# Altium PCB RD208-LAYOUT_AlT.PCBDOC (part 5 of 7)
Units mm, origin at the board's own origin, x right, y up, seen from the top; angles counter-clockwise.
Board outline 240 x 150 mm, 6 copper layers (TOP, Mid-Layer 1, Mid-Layer 2, Mid-Layer 3, Mid-Layer 4, BOTTOM), stack 1.422 mm thick; 773 components, 409 nets, 3936 pads, 97 vias.
Unrouted connection lines stored in the file: 1.
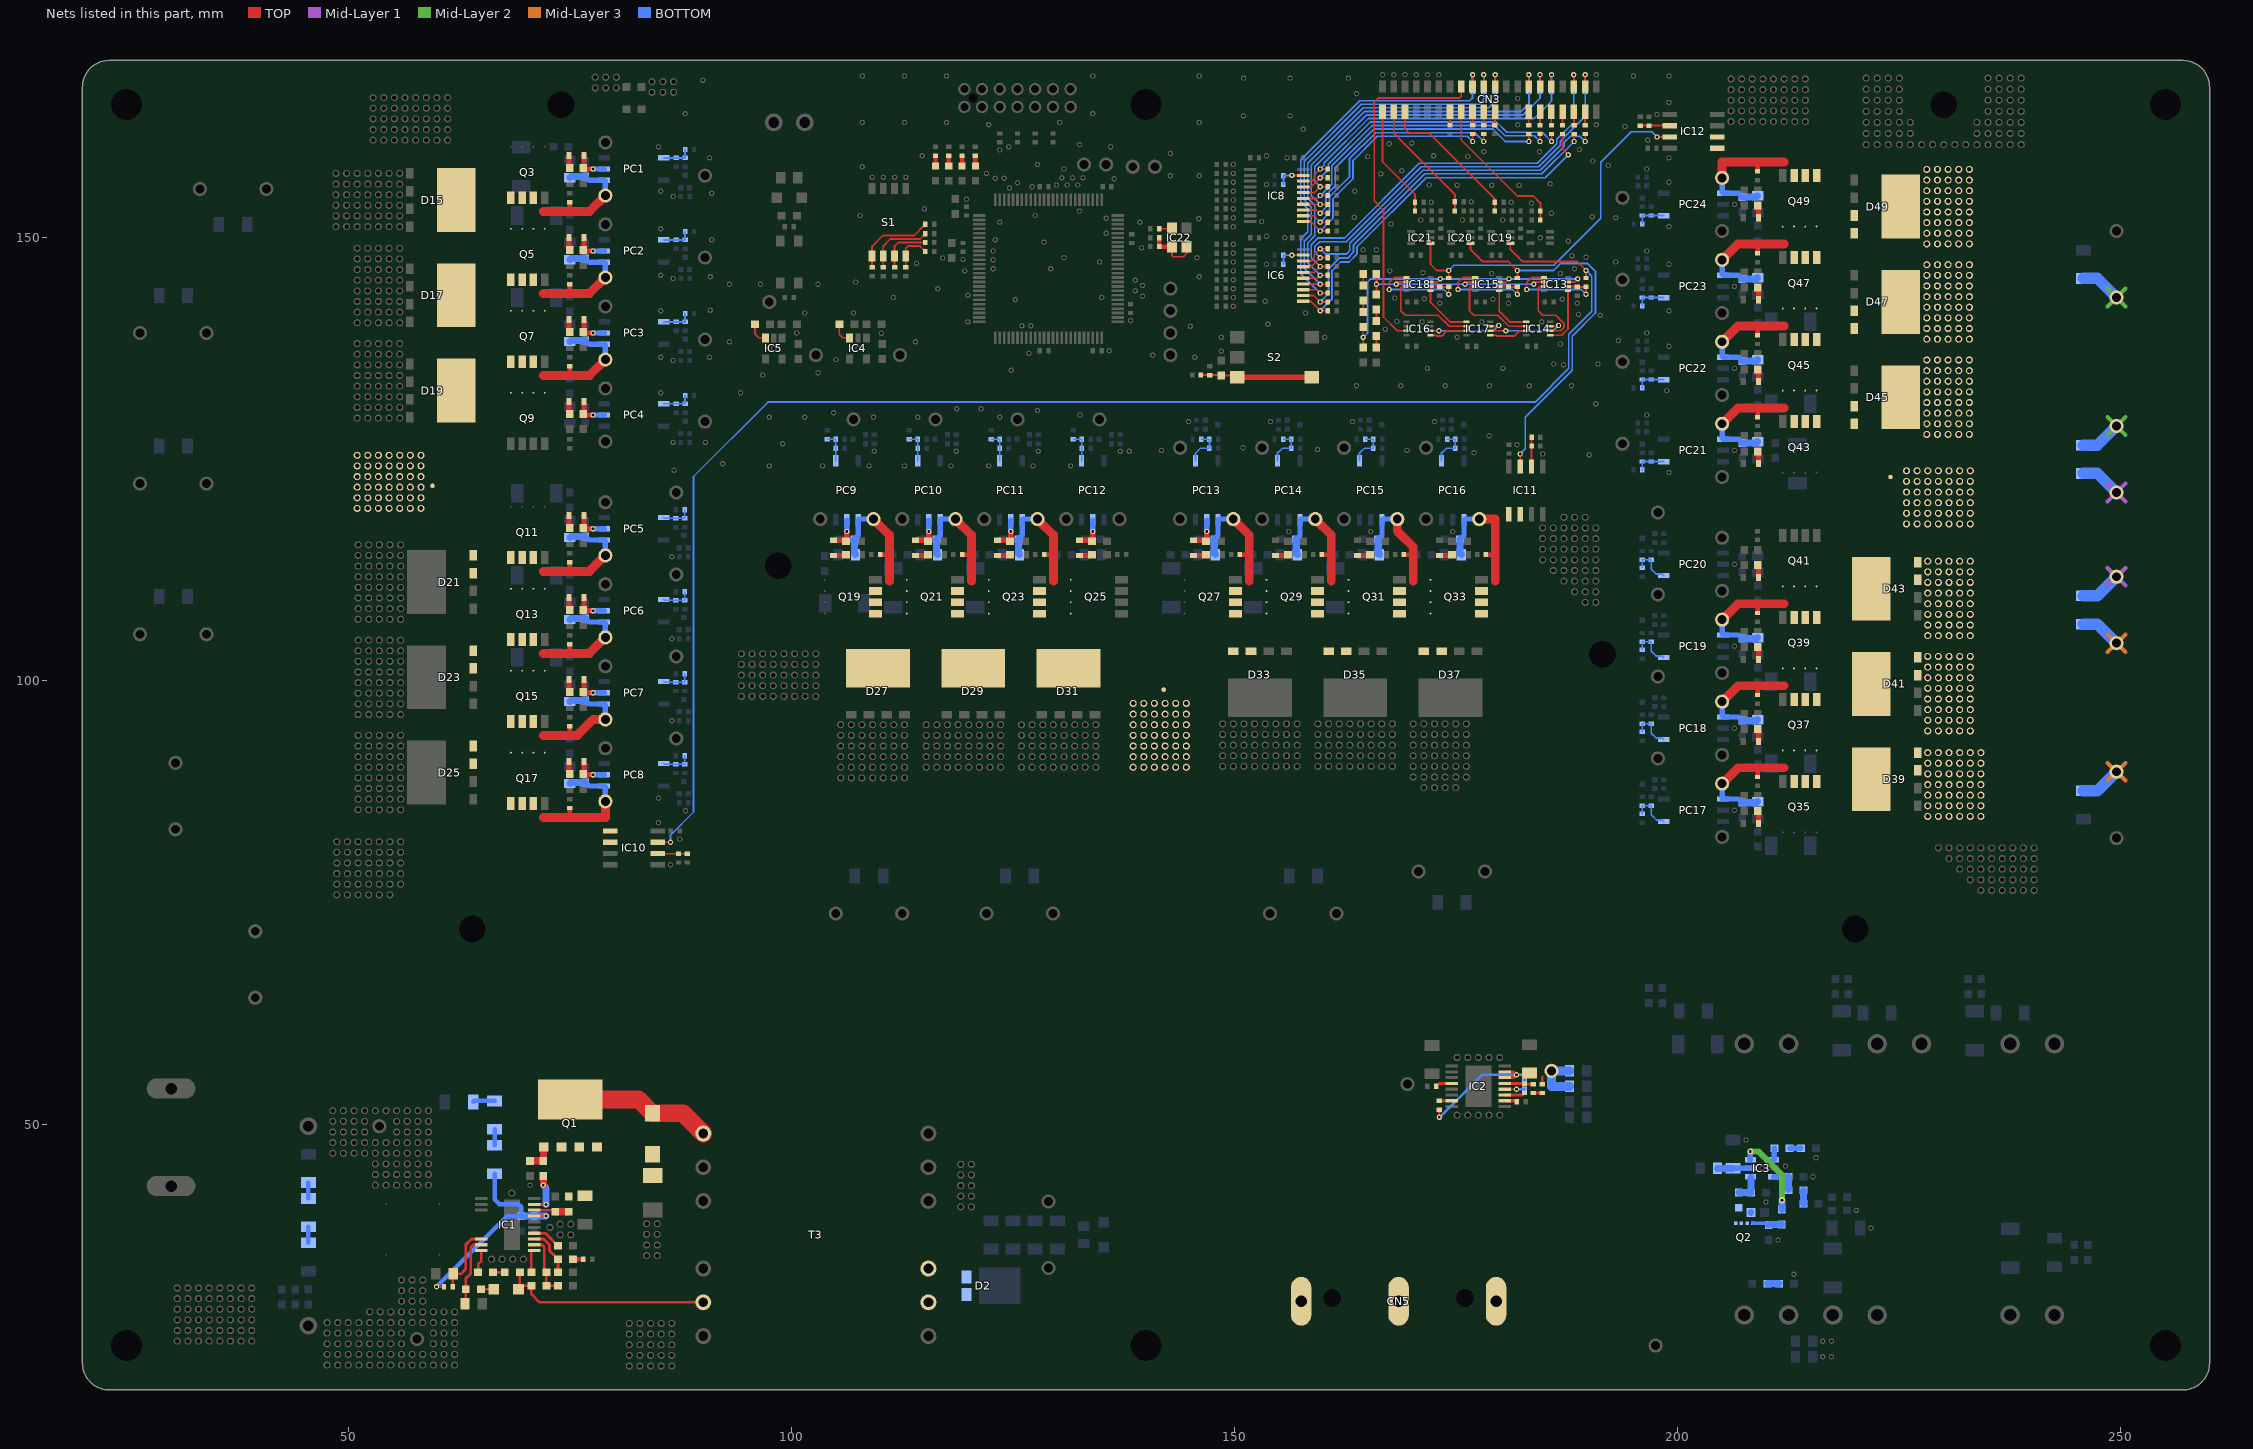
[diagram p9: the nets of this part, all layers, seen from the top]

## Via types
v1: diameter 0.7, hole 0.3, TOP to BOTTOM, 92 vias
v2: diameter 0.9, hole 0.5, TOP to BOTTOM, 4 vias
v3: diameter 1.6, hole 1, TOP to BOTTOM, 1 vias

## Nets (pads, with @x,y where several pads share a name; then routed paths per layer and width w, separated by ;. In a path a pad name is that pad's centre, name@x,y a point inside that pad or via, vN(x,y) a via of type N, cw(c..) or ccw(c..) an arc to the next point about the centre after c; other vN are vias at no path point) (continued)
HVW_1_4: C82.2 C84.1 D43.3 D43.4 D49.5 pad.@228.1,149.3 pad.@228.1,150.5 pad.@228.1,151.7 pad.@228.1,152.9 pad.@228.1,154.1 pad.@228.1,155.3 pad.@228.1,156.5 pad.@228.1,157.7 pad.@228.2,105.1 pad.@228.2,106.3 pad.@228.2,107.5 pad.@228.2,108.7 pad.@228.2,109.9 pad.@228.2,111.1 pad.@228.2,112.3 pad.@228.2,113.5 pad.@229.3,149.3 pad.@229.3,150.5 pad.@229.3,151.7 pad.@229.3,152.9 pad.@229.3,154.1 pad.@229.3,155.3 pad.@229.3,156.5 pad.@229.3,157.7 pad.@229.4,105.1 pad.@229.4,106.3 pad.@229.4,107.5 pad.@229.4,108.7 pad.@229.4,109.9 pad.@229.4,111.1 pad.@229.4,112.3 pad.@229.4,113.5 pad.@230.5,149.3 pad.@230.5,150.5 pad.@230.5,151.7 pad.@230.5,152.9 pad.@230.5,154.1 pad.@230.5,155.3 pad.@230.5,156.5 pad.@230.5,157.7 pad.@230.6,105.1 pad.@230.6,106.3 pad.@230.6,107.5 pad.@230.6,108.7 pad.@230.6,109.9 pad.@230.6,111.1 pad.@230.6,112.3 pad.@230.6,113.5 pad.@231.7,149.3 pad.@231.7,150.5 pad.@231.7,151.7 pad.@231.7,152.9 pad.@231.7,154.1 pad.@231.7,155.3 pad.@231.7,156.5 pad.@231.7,157.7 pad.@231.8,105.1 pad.@231.8,106.3 pad.@231.8,107.5 pad.@231.8,108.7 pad.@231.8,109.9 pad.@231.8,111.1 pad.@231.8,112.3 pad.@231.8,113.5 pad.@232.9,149.3 pad.@232.9,150.5 pad.@232.9,151.7 pad.@232.9,152.9 pad.@232.9,154.1 pad.@232.9,155.3 pad.@232.9,156.5 pad.@232.9,157.7 pad.@233,105.1 pad.@233,106.3 pad.@233,107.5 pad.@233,108.7 pad.@233,109.9 pad.@233,111.1 pad.@233,112.3 pad.@233,113.5 R205.2 R206.1 | length 20.6
  Mid-Layer 2 w0.44: 248.5,127.75 C82.2@249.5,128.75 ; 248.5,129.75 C82.2@249.5,128.75 ; 248.5,142.25 C84.1@249.5,143.25 ; 248.5,144.25 C84.1@249.5,143.25 ; 250.5,127.75 C82.2@249.5,128.75 ; 250.5,129.75 C82.2@249.5,128.75 ; 250.5,142.25 C84.1@249.5,143.25 ; 250.5,144.25 C84.1@249.5,143.25
  BOTTOM w1.3: R205.2@245.75,126.6 247.35,126.6 C82.2@249.5,128.75 ; R206.1@245.75,145.4 247.35,145.4 C84.1@249.5,143.25
HVW_2_4: C80.2 C82.1 D41.3 D41.4 D47.5 pad.@228.1,138.55 pad.@228.1,139.75 pad.@228.1,140.95 pad.@228.1,142.15 pad.@228.1,143.35 pad.@228.1,144.55 pad.@228.1,145.75 pad.@228.1,146.95 pad.@228.2,94.35 pad.@228.2,95.55 pad.@228.2,96.75 pad.@228.2,97.95 pad.@228.2,99.15 pad.@228.2,100.35 pad.@228.2,101.55 pad.@228.2,102.75 pad.@229.3,138.55 pad.@229.3,139.75 pad.@229.3,140.95 pad.@229.3,142.15 pad.@229.3,143.35 pad.@229.3,144.55 pad.@229.3,145.75 pad.@229.3,146.95 pad.@229.4,94.35 pad.@229.4,95.55 pad.@229.4,96.75 pad.@229.4,97.95 pad.@229.4,99.15 pad.@229.4,100.35 pad.@229.4,101.55 pad.@229.4,102.75 pad.@230.5,138.55 pad.@230.5,139.75 pad.@230.5,140.95 pad.@230.5,142.15 pad.@230.5,143.35 pad.@230.5,144.55 pad.@230.5,145.75 pad.@230.5,146.95 pad.@230.6,94.35 pad.@230.6,95.55 pad.@230.6,96.75 pad.@230.6,97.95 pad.@230.6,99.15 pad.@230.6,100.35 pad.@230.6,101.55 pad.@230.6,102.75 pad.@231.7,138.55 pad.@231.7,139.75 pad.@231.7,140.95 pad.@231.7,142.15 pad.@231.7,143.35 pad.@231.7,144.55 pad.@231.7,145.75 pad.@231.7,146.95 pad.@231.8,94.35 pad.@231.8,95.55 pad.@231.8,96.75 pad.@231.8,97.95 pad.@231.8,99.15 pad.@231.8,100.35 pad.@231.8,101.55 pad.@231.8,102.75 pad.@232.9,138.55 pad.@232.9,139.75 pad.@232.9,140.95 pad.@232.9,142.15 pad.@232.9,143.35 pad.@232.9,144.55 pad.@232.9,145.75 pad.@232.9,146.95 pad.@233,94.35 pad.@233,95.55 pad.@233,96.75 pad.@233,97.95 pad.@233,99.15 pad.@233,100.35 pad.@233,101.55 pad.@233,102.75 R204.2 R205.1 | length 20.6
  Mid-Layer 1 w0.44: 248.5,110.75 C80.2@249.5,111.75 ; 248.5,112.75 C80.2@249.5,111.75 ; 248.5,120.25 C82.1@249.5,121.25 ; 248.5,122.25 C82.1@249.5,121.25 ; 250.5,110.75 C80.2@249.5,111.75 ; 250.5,112.75 C80.2@249.5,111.75 ; 250.5,120.25 C82.1@249.5,121.25 ; 250.5,122.25 C82.1@249.5,121.25
  BOTTOM w1.3: R204.2@245.75,109.6 247.35,109.6 C80.2@249.5,111.75 ; R205.1@245.75,123.4 247.35,123.4 C82.1@249.5,121.25
HVW_3_4: C78.2 C80.1 D39.3 D39.4 D45.5 pad.@228.1,127.8 pad.@228.1,129 pad.@228.1,130.2 pad.@228.1,131.4 pad.@228.1,132.6 pad.@228.1,133.8 pad.@228.1,135 pad.@228.1,136.2 pad.@228.2,84.7 pad.@228.2,85.9 pad.@228.2,87.1 pad.@228.2,88.3 pad.@228.2,89.5 pad.@228.2,90.7 pad.@228.2,91.9 pad.@229.3,127.8 pad.@229.3,129 pad.@229.3,130.2 pad.@229.3,131.4 pad.@229.3,132.6 pad.@229.3,133.8 pad.@229.3,135 pad.@229.3,136.2 pad.@229.4,84.7 pad.@229.4,85.9 pad.@229.4,87.1 pad.@229.4,88.3 pad.@229.4,89.5 pad.@229.4,90.7 pad.@229.4,91.9 pad.@230.5,127.8 pad.@230.5,129 pad.@230.5,130.2 pad.@230.5,131.4 pad.@230.5,132.6 pad.@230.5,133.8 pad.@230.5,135 pad.@230.5,136.2 pad.@230.6,84.7 pad.@230.6,85.9 pad.@230.6,87.1 pad.@230.6,88.3 pad.@230.6,89.5 pad.@230.6,90.7 pad.@230.6,91.9 pad.@231.7,127.8 pad.@231.7,129 pad.@231.7,130.2 pad.@231.7,131.4 pad.@231.7,132.6 pad.@231.7,133.8 pad.@231.7,135 pad.@231.7,136.2 pad.@231.8,84.7 pad.@231.8,85.9 pad.@231.8,87.1 pad.@231.8,88.3 pad.@231.8,89.5 pad.@231.8,90.7 pad.@231.8,91.9 pad.@232.9,127.8 pad.@232.9,129 pad.@232.9,130.2 pad.@232.9,131.4 pad.@232.9,132.6 pad.@232.9,133.8 pad.@232.9,135 pad.@232.9,136.2 pad.@233,84.7 pad.@233,85.9 pad.@233,87.1 pad.@233,88.3 pad.@233,89.5 pad.@233,90.7 pad.@233,91.9 pad.@234.2,84.7 pad.@234.2,85.9 pad.@234.2,87.1 pad.@234.2,88.3 pad.@234.2,89.5 pad.@234.2,90.7 pad.@234.2,91.9 R203.2 R204.1 | length 20.6
  Mid-Layer 3 w0.44: 248.5,88.75 C78.2@249.5,89.75 ; 248.5,90.75 C78.2@249.5,89.75 ; 248.5,103.25 C80.1@249.5,104.25 ; 248.5,105.25 C80.1@249.5,104.25 ; 250.5,88.75 C78.2@249.5,89.75 ; 250.5,90.75 C78.2@249.5,89.75 ; 250.5,103.25 C80.1@249.5,104.25 ; 250.5,105.25 C80.1@249.5,104.25
  BOTTOM w1.3: R203.2@245.75,87.6 247.35,87.6 C78.2@249.5,89.75 ; R204.1@245.75,106.4 247.35,106.4 C80.1@249.5,104.25
ILIM_H: IC13.3 IC15.3 IC18.3 pad.@164.5,138.75 pad.@173.2,145.35 pad.@180.95,145.35 pad.@188.7,145.35 R129.2 R131.1 | length 36.3
  TOP w0.2: R129.2@164.5,137.6 pad.@164.5,138.75 R131.1@164.5,139.9 ; IC18.3@172.1,145 172.85,145 pad.@173.2,145.35 ; IC15.3@179.85,145 180.6,145 pad.@180.95,145.35 ; IC13.3@187.6,145 188.35,145 pad.@188.7,145.35
  BOTTOM w0.2: pad.@164.5,138.75 165,139.25 165,145 165.35,145.35 pad.@173.2,145.35 pad.@180.95,145.35 pad.@188.7,145.35
ILIM_L: IC13.6 IC15.6 IC18.6 pad.@166,144.75 pad.@168.25,144.75 pad.@176,144.75 pad.@183.75,144.75 R132.2 R134.1 | length 23.8
  TOP w0.2: R132.2@166,143.6 pad.@166,144.75 R134.1@166,145.9 ; pad.@168.25,144.75 168.5,145 IC18.6@169.4,145 ; pad.@176,144.75 176.25,145 IC15.6@177.15,145 ; pad.@183.75,144.75 184,145 IC13.6@184.9,145
  BOTTOM w0.2: pad.@166,144.75 pad.@168.25,144.75 pad.@176,144.75 pad.@183.75,144.75
ISEN_U: IC10.7 IC19.1 pad.@86.35,81.785 pad.@189.65,146.3 R309.2 | length 171
  TOP w0.2: IC10.7@84.932,81.785 pad.@86.35,81.785 ; IC19.1@181.1,149.35 181.1,148.7 182.5,147.3 188.65,147.3 pad.@189.65,146.3 R309.2@189.65,145.45
  BOTTOM w0.2: pad.@86.35,81.785 86.35,82.6 88.95,85.2 88.95,123.05 97.35,131.45 183.9,131.45 187.7,135.25 187.7,139.1 190.3,141.7 190.3,145.65 pad.@189.65,146.3
ISEN_U_FLT: C139.1 IC13.2 IC13.5 pad.@182.95,144.15 pad.@189.65,143.6 R309.1 | length 12.8
  TOP w0.2: pad.@182.95,144.15 182.95,144.95 183.5,145.5 IC13.5@184.9,145.5 ; IC13.2@187.6,144.5 188.6,144.5 C139.1@188.65,144.45 R309.1@189.65,144.45 pad.@189.65,143.6
  BOTTOM w0.2: pad.@182.95,144.15 189.1,144.15 pad.@189.65,143.6
ISEN_V: IC11.7 IC20.1 pad.@181.9,146.3 pad.@182.215,125.6 R310.2 | length 42.8
  TOP w0.2: IC20.1@176.6,149.35 176.6,148.7 178,147.3 180.9,147.3 pad.@181.9,146.3 R310.2@181.9,145.45 ; IC11.7@182.215,124.182 pad.@182.215,125.6
  BOTTOM w0.2: pad.@181.9,146.3 186,146.3 186.8,147.1 189.8,147.1 190.7,146.2 190.7,141.5 188.1,138.9 188.1,135.05 182.8,129.75 182.8,126.185 pad.@182.215,125.6
ISEN_V_FLT: C140.1 IC15.2 IC15.5 pad.@175.2,144.15 pad.@181.9,143.6 R310.1 | length 12.8
  TOP w0.2: pad.@175.2,144.15 175.2,144.95 175.75,145.5 IC15.5@177.15,145.5 ; IC15.2@179.85,144.5 180.85,144.5 C140.1@180.9,144.45 R310.1@181.9,144.45 pad.@181.9,143.6
  BOTTOM w0.2: pad.@175.2,144.15 181.35,144.15 pad.@181.9,143.6
ISEN_W: IC12.7 IC21.1 pad.@174.15,146.3 pad.@197.65,161.365 R311.2 | length 40.9
  TOP w0.2: IC21.1@172.1,149.35 172.1,147 172.8,146.3 pad.@174.15,146.3 R311.2@174.15,145.45 ; pad.@197.65,161.365 IC12.7@199.067,161.365
  BOTTOM w0.2: pad.@174.15,146.3 174.75,146.9 186,146.9 191.3,152.2 191.3,158.5 194.75,161.95 197.065,161.95 pad.@197.65,161.365
ISEN_W_FLT: C141.1 IC18.2 IC18.5 pad.@167.45,144.15 pad.@174.15,143.6 R311.1 | length 12.8
  TOP w0.2: pad.@167.45,144.15 167.45,144.95 168,145.5 IC18.5@169.4,145.5 ; IC18.2@172.1,144.5 173.1,144.5 C141.1@173.15,144.45 R311.1@174.15,144.45 pad.@174.15,143.6
  BOTTOM w0.2: pad.@167.45,144.15 173.6,144.15 pad.@174.15,143.6
L3803_FB: IC3.3 R29.2 R34.1 | length 3.1
  BOTTOM w0.6: IC3.3@210.81,44.05 R34.1@212.5,44.05
  BOTTOM w0.8: R29.2@212.5,42.6 R34.1@212.5,44.05
L3803_NGATE: IC3.6 R154.1 | length 9.5
  Mid-Layer 2 w0.7: v1(208.19,46.9) 209.1,46.9 211.75,44.25 v1(211.75,41.4)
  BOTTOM w0.6: IC3.6@208.19,45.95 v1(208.19,46.9)
  BOTTOM w0.8: R154.1@211.75,40.35 v1(211.75,41.4)
L3803_SENSE: C103.1 IC3.4 R30.1 | length 3.1
  BOTTOM w0.8: R30.1@206.9,42.25 C103.1@208.25,42.25 IC3.4@208.25,43.95
L3803_VCC: C129.1 IC3.5 R155.2 | length 3.7
  BOTTOM w0.6: C129.1@206.25,45 IC3.5@208.19,45
  BOTTOM w0.8: R155.2@204.475,45 C129.1@206.25,45
LDO_15V_CDC: IC2.3 R296.1 | length 2.3
  TOP w0.3: IC2.3@180.488,53.275 182.475,53.275 R296.1@182.7,53.5
LDO_15V_ILIM: IC2.2 R26.1 | length 1.4
  TOP w0.35: IC2.2@180.488,52.625 181.725,52.625 R26.1@181.85,52.5
LDO_15V_SET: IC2.5 R27.2 R296.2 | length 3.2
  TOP w0.3: IC2.5@180.488,54.575 182.625,54.575 R296.2@182.7,54.5 R27.2@183.7,54.5
LDO_15V_STD_N: IC2.12 R22.2 | length 1.9
  TOP w0.3: R22.2@172.75,54.25 173.075,54.575 IC2.12@174.513,54.575
LDO_15VOUT: C16.1 IC2.6 IC2.7 pad.@173.1,50.75 pad.@181.8,55.55 R21.1 R24.2 R25.1 R295.1 R297.2 TP4.1 | length 22.5
  TOP w0.3: pad.@173.1,50.75 R295.1@173.1,51.6 ; R24.2@184.7,54.5 184.7,55.35
  TOP w0.35: IC2.6@180.488,55.225 181.475,55.225 pad.@181.8,55.55 181.475,55.875 IC2.7@180.488,55.875
  BOTTOM w0.3: pad.@173.1,50.75 177.9,55.55 pad.@181.8,55.55 182.55,55.55 182.7,55.4 R297.2@182.7,54.95
  BOTTOM w1: R25.1@187.775,54.25 185.75,54.25 TP4.1@185.75,56 R21.1@187.775,56
LT8316_BIAS: C4.1 IC1.9 R2.1 | length 8
  TOP w0.3: C4.1@63.175,29.7 63.25,29.775 R2.1@63.25,31.35 63.25,32.55 63.8,33.1 63.8,36.05 64.125,36.375 IC1.9@65.012,36.375
LT8316_DCM: IC1.10 R4.2 | length 2.6
  TOP w0.3: R4.2@64.65,33.25 64.65,34.2 65.012,34.562 IC1.10@65.012,35.725
LT8316_EN: C8.2 IC1.17 pad.@59.95,31.65 pad.@72.3,39.625 R7.2 R11.2 R312.2 | length 25.1
  TOP w0.3: pad.@59.95,31.65 R312.2@60.8,31.65 ; IC1.17@70.988,39.625 pad.@72.3,39.625
  BOTTOM w0.5: pad.@59.95,31.65 67.9,39.6 R11.2@69.5,39.6 69.5,40.65 69.2,40.95 67.05,40.95 66.5,41.5 R7.2@66.5,44.4
  BOTTOM w0.8: R11.2@69.5,39.6 C8.2@71,39.6 71.025,39.625 pad.@72.3,39.625
LT8316_FB: IC1.12 R6.2 R12.1 R13.1 | length 7
  TOP w0.3: IC1.12@70.988,36.375 71.875,36.375 72.1,36.15 72.1,33.5 R12.1@72.35,33.25 R6.2@72.35,31.75 R13.1@73.65,31.75
LT8316_FB_B: C5.1 D1.1 R6.1 T3.5 | length 24.3
  TOP w0.3: C5.1@69.35,33.25 D1.1@69.35,31.5 ; T3.5@90.05,29.88 71.57,29.88 70.65,30.8 R6.1@70.65,31.75 69.6,31.75 D1.1@69.35,31.5 ; D1.1@69.35,31.5 D1.1@69.2,31.35 D1.1@69.35,31.5
LT8316_GATE: IC1.19 pad.@72,43.1 pad.@72.3,40.925 R17.1 | length 4.7
  TOP w0.3: IC1.19@70.988,40.925 pad.@72.3,40.925
  TOP w0.8: pad.@72,43.1 R17.1@72,44.15
  BOTTOM w0.8: pad.@72,43.1 72.3,42.8 pad.@72.3,40.925
LT8316_GATE_B: Q1.1 R17.2 R207.1 | length 3.1
  TOP w0.8: R207.1@70.5,45.85 R17.2@72,45.85 72,47.375 Q1.1@72.05,47.425
LT8316_INTVCC: C14.1 IC1.8 R312.1 | length 7.9
  TOP w0.3: R312.1@61.8,31.65 61.8,33.075 C14.1@61.825,33.1 62.7,33.1 63.25,33.65 63.25,36.375 63.9,37.025 IC1.8@65.012,37.025
LT8316_IREG: IC1.14 R16.2 | length 3.3
  TOP w0.3: IC1.14@70.988,37.675 72.225,37.675 R16.2@73.65,36.25
LT8316_SENSE: C13.1 IC1.18 R18.1 | length 3.9
  TOP w0.3: IC1.18@70.988,40.275 73.175,40.275 C13.1@73.35,40.1
  TOP w0.8: C13.1@73.35,40.1 R18.1@74.85,40.1
LT8316_SENSE_B: Q1.2 Q1.3 Q1.4 R18.2 R19.1
LT8316_TC: IC1.11 R12.2 | length 2.8
  TOP w0.3: R12.2@70.65,33.25 70.65,35.725 IC1.11@70.988,35.725
LT8316_VC: C10.1 IC1.13 R14.1 | length 5.5
  TOP w0.3: IC1.13@70.988,37.025 72.05,37.025 72.7,36.375 72.7,35.7 R14.1@73.65,34.75 C10.1@73.65,33.25
MCU_EMG: CN3.25 IC16.7 | length 39.1
  TOP w0.2: IC16.7@169.4,139.5 168.35,139.5 166.8,141.05 166.8,153.1 165.75,154.15 165.75,165.3 166.2,165.75 175.35,165.75 175.575,165.975 CN3.25@175.575,167.075
MCU_IU: C134.1 CN3.36 R137.1 | length 16.7
  TOP w0.2: CN3.36@169.225,164.205 169.225,162.275 169.65,161.85 171.9,161.85 179.35,154.4 C134.1@179.35,154 R137.1@179.35,153
MCU_IV: C135.1 CN3.38 R140.1 | length 14.1
  TOP w0.2: CN3.38@167.955,164.205 167.955,161.795 174.85,154.9 C135.1@174.85,154.05 R140.1@174.85,153
MCU_IW: C136.1 CN3.40 R143.1 | length 12.7
  TOP w0.2: CN3.40@166.685,164.205 166.685,158.565 170.35,154.9 C136.1@170.35,154 R143.1@170.35,153
MCU_MODE: IC6.14 pad.@159.65,144.75 R44.2 R166.1 | length 42
  TOP w0.2: IC6.14@157.75,144.775 159.201,144.775 pad.@159.65,144.75 R44.2@160.5,144.75
  BOTTOM w0.2: pad.@159.65,144.75 157.85,146.55 157.85,149.6 158.65,150.4 158.65,153.45 157.85,154.25 157.85,158.6 164.3,165.05 177.6,165.05 178.1,165.55 R166.1@178.1,166.45
MCU_RESET: IC6.13 pad.@159.65,143.75 R45.2 R167.1 | length 42.5
  TOP w0.2: IC6.13@157.75,144.125 159.275,144.125 pad.@159.65,143.75 R45.2@160.5,143.75
  BOTTOM w0.2: pad.@159.65,143.75 157.45,145.95 157.45,149.85 158.25,150.65 158.25,153.25 157.45,154.05 157.45,158.8 164.1,165.45 176.5,165.45 176.85,165.8 R167.1@176.85,166.45
MCU_RSV1: IC6.12 pad.@159.65,142.75 pad.@188.3,160.85 R46.2 R198.2 | length 42.2
  TOP w0.2: IC6.12@157.75,143.475 158.925,143.475 pad.@159.65,142.75 R46.2@160.5,142.75 ; pad.@188.3,160.85 R198.2@188.3,161.7
  BOTTOM w0.2: pad.@159.65,142.75 160.6,143.7 160.6,146.5 161.8,147.7 162.75,147.7 163.4,148.35 163.4,149.15 171.45,157.2 184.65,157.2 pad.@188.3,160.85
MCU_RSV2: IC6.11 pad.@159.65,141.75 pad.@187.65,159.35 R47.2 R238.2 | length 43.4
  TOP w0.2: IC6.11@157.75,142.825 158.575,142.825 pad.@159.65,141.75 R47.2@160.5,141.75 ; R238.2@187,161.7 187,160 pad.@187.65,159.35
  BOTTOM w0.2: pad.@159.65,141.75 161,143.1 161,146.3 161.95,147.25 162.9,147.25 163.8,148.15 163.8,148.95 171.6,156.75 185.05,156.75 pad.@187.65,159.35
MCU_RSV3: IC8.12 pad.@159.65,151.75 pad.@178.1,160.85 R64.2 R239.2 | length 29.2
  TOP w0.2: IC8.12@157.75,152.475 158.925,152.475 pad.@159.65,151.75 R64.2@160.5,151.75 ; pad.@178.1,160.85 R239.2@178.1,161.7
  BOTTOM w0.2: pad.@159.65,151.75 160.7,152.8 160.7,154.6 162.95,156.85 162.95,158.9 165.9,161.85 177.1,161.85 pad.@178.1,160.85
MCU_RSV4: IC8.11 pad.@159.65,150.75 pad.@176.85,160.85 R65.2 R240.2 | length 28.4
  TOP w0.2: IC8.11@157.75,151.825 158.575,151.825 pad.@159.65,150.75 R65.2@160.5,150.75 ; pad.@176.85,160.85 R240.2@176.85,161.7
  BOTTOM w0.2: pad.@159.65,150.75 161.1,152.2 161.1,154.4 163.35,156.65 163.35,158.7 166.1,161.45 176.25,161.45 pad.@176.85,160.85
MCU_TCK: IC6.17 pad.@159.65,147.75 R41.2 R160.1 | length 44.3
  TOP w0.2: IC6.17@157.75,146.725 158.625,146.725 pad.@159.65,147.75 R41.2@160.5,147.75
  BOTTOM w0.2: pad.@159.65,147.75 159.05,148.35 159.05,149 159.6,149.55 162.6,149.55 171.05,158 184.314,158 186.75,160.436 186.75,160.9 189.55,163.7 R160.1@189.55,166.45
MCU_TDI: IC6.16 pad.@159.65,146.75 R42.2 R161.1 | length 45
  TOP w0.2: IC6.16@157.75,146.075 158.975,146.075 pad.@159.65,146.75 R42.2@160.5,146.75
  BOTTOM w0.2: pad.@159.65,146.75 158.65,147.75 158.65,149.2 159.4,149.95 162.4,149.95 170.85,158.4 184.149,158.4 186.35,160.601 186.35,161.1 188.25,163 R161.1@188.25,166.45
MCU_TDO: IC6.18 pad.@159.65,148.75 pad.@189.55,160.85 R40.2 R156.2 | length 41
  TOP w0.2: IC6.18@157.75,147.375 158.7,147.375 158.975,147.65 158.975,148.075 pad.@159.65,148.75 R40.2@160.5,148.75 ; pad.@189.55,160.85 R156.2@189.55,161.7
  BOTTOM w0.2: pad.@159.65,148.75 160.25,148.15 162.6,148.15 163,148.55 163,149.35 171.25,157.6 184.48,157.6 187.15,160.27 187.15,160.7 187.9,161.45 188.95,161.45 pad.@189.55,160.85
MCU_TMS: IC6.15 pad.@159.65,145.75 R43.2 R165.1 | length 41.9
  TOP w0.2: IC6.15@157.75,145.425 159.325,145.425 pad.@159.65,145.75 R43.2@160.5,145.75
  BOTTOM w0.2: pad.@159.65,145.75 158.25,147.15 158.25,149.4 159.05,150.2 159.05,153.65 158.25,154.45 158.25,158.4 164.5,164.65 178.65,164.65 179.4,165.4 R165.1@179.4,166.45
MCU_UH: IC8.18 pad.@159.65,157.75 R58.2 R162.1 | length 34
  TOP w0.2: IC8.18@157.75,156.375 158.7,156.375 158.975,156.65 158.975,157.075 pad.@159.65,157.75 R58.2@160.5,157.75
  BOTTOM w0.2: pad.@159.65,157.75 160.1,158.2 160.1,158.45 165.1,163.45 183.8,163.45 185.75,165.4 R162.1@185.75,166.45
MCU_UL: IC8.17 pad.@159.65,156.75 pad.@185.75,160.85 R59.2 R157.2 | length 34
  TOP w0.2: IC8.17@157.75,155.725 158.625,155.725 pad.@159.65,156.75 R59.2@160.5,156.75 ; pad.@185.75,160.85 R157.2@185.75,161.7
  BOTTOM w0.2: pad.@159.65,156.75 160.55,157.65 160.55,158.3 165.3,163.05 179.55,163.05 180.7,161.9 184.7,161.9 pad.@185.75,160.85
MCU_VDC: C133.1 CN3.26 R192.2 | length 17
  TOP w0.2: CN3.26@175.575,164.205 175.575,161.025 181.9,154.7 183.7,154.7 184.5,153.9 C133.1@184.5,153 R192.2@184.5,152
MCU_VH: IC8.16 pad.@159.65,155.75 R60.2 R163.1 | length 34.8
  TOP w0.2: IC8.16@157.75,155.075 158.975,155.075 pad.@159.65,155.75 R60.2@160.5,155.75
  BOTTOM w0.2: pad.@159.65,155.75 159.05,156.35 159.05,158 164.9,163.85 182.55,163.85 184.45,165.75 R163.1@184.45,166.45
MCU_VL: IC8.15 pad.@159.65,154.75 pad.@184.45,160.85 R61.2 R158.2 | length 33.8
  TOP w0.2: IC8.15@157.75,154.425 159.325,154.425 pad.@159.65,154.75 R61.2@160.5,154.75 ; pad.@184.45,160.85 R158.2@184.45,161.7
  BOTTOM w0.2: pad.@159.65,154.75 160.95,156.05 160.95,158.1 165.5,162.65 179.35,162.65 180.5,161.5 183.8,161.5 pad.@184.45,160.85
MCU_WH: IC8.14 pad.@159.65,153.75 R62.2 R164.1 | length 36.4
  TOP w0.2: IC8.14@157.75,153.775 159.201,153.775 pad.@159.65,153.75 R62.2@160.5,153.75
  BOTTOM w0.2: pad.@159.65,153.75 158.65,154.75 158.65,158.2 164.7,164.25 182.35,164.25 183.2,165.1 R164.1@183.2,166.45
MCU_WL: IC8.13 pad.@159.65,152.75 pad.@183.2,160.85 R63.2 R159.2 | length 33.8
  TOP w0.2: IC8.13@157.75,153.125 159.275,153.125 pad.@159.65,152.75 R63.2@160.5,152.75 ; pad.@183.2,160.85 R159.2@183.2,161.7
  BOTTOM w0.2: pad.@159.65,152.75 160.3,153.4 160.3,154.8 161.35,155.85 161.35,157.9 165.7,162.25 179.15,162.25 180.55,160.85 pad.@183.2,160.85
N757857: D6.A Q1.5 T3.1 | length 16.6
  TOP w2: Q1.5@75.05,52.775 82.75,52.775 D6.A@84.3,51.225 87.755,51.225 T3.1@90.05,48.93
N3161846: Q2.1 Q2.2 Q2.3 R30.2 R33.1 | length 0
  BOTTOM w0.8: R33.1@208.24,40 R33.1@208.25,40.01
N3164696: C22.1 IC3.1 | length 1.3
  BOTTOM w0.6: IC3.1@210.81,45.95 210.9,46.04 C22.1@210.9,47.25
N3166714: C22.2 R32.1 | length 1.3
  BOTTOM w0.6: C22.2@212.6,47.25 R32.1@213.9,47.25
N15775681: R131.2 R133.1 | length 1.3
  TOP w0.2: R131.2@164.5,141.6 R133.1@164.5,142.9
N15775685: R133.2 R135.1 | length 1.3
  TOP w0.2: R133.2@164.5,144.6 R135.1@164.5,145.9
N15775892: R130.2 R132.1 | length 1.3
  TOP w0.2: R130.2@166,140.6 R132.1@166,141.9
N15776035: R128.2 R130.1 | length 1.3
  TOP w0.2: R128.2@166,137.6 R130.1@166,138.9
N15787951: IC6.19 pad.@156.45,148.025 R241.2 R242.2 | length 3.3
  TOP w0.2: pad.@156.45,148.025 IC6.19@157.75,148.025
  BOTTOM w0.2: R242.2@155.5,147 R241.2@155.5,148 155.525,148.025 pad.@156.45,148.025
N15791319: IC8.19 pad.@156.45,157.025 R243.2 R244.2 | length 3.3
  TOP w0.2: pad.@156.45,157.025 IC8.19@157.75,157.025
  BOTTOM w0.2: R244.2@155.5,156 R243.2@155.5,157 155.525,157.025 pad.@156.45,157.025
N15816177: CN3.20 R56.1 | length 1.5
  TOP w0.2: R56.1@179.35,162.7 179.385,162.735 CN3.20@179.385,164.205
N15836565: CN3.28 R57.1 | length 1.5
  TOP w0.2: R57.1@174.305,162.7 CN3.28@174.305,164.205
N15837078: CN3.10 R157.1 | length 1.5
  TOP w0.2: R157.1@185.735,162.715 CN3.10@185.735,164.205
N15837084: CN3.12 R158.1 | length 1.5
  TOP w0.2: R158.1@184.465,162.7 CN3.12@184.465,164.205
N15837090: CN3.14 R159.1 | length 1.5
  TOP w0.2: R159.1@183.195,162.705 CN3.14@183.195,164.205
N15837096: CN3.4 R156.1 | length 1.5
  TOP w0.2: R156.1@189.545,162.705 CN3.4@189.545,164.205
N15859536: IC10.6 R289.1 R290.1 | length 3.3
  TOP w0.2: IC10.6@84.932,80.515 84.948,80.5 R290.1@87.25,80.5 R289.1@88.25,80.5
N15862955: IC12.6 R293.1 R294.2 | length 3.3
  TOP w0.2: R293.1@195.75,162.65 R294.2@196.75,162.65 IC12.6@199.053,162.65
N15947158: R9.2 R10.1 | length 1.8
  BOTTOM w0.5: R10.1@45.5,36.6 R9.2@45.5,38.4
N15947162: R5.2 R9.1 | length 1.8
  BOTTOM w0.5: R9.1@45.5,41.6 R5.2@45.5,43.4
N15947280: R1.2 R3.1 | length 2.4
  BOTTOM w0.5: R1.2@64.1,52.5 64.2,52.6 R3.1@66.5,52.6
N15947304: R3.2 R7.1 | length 1.8
  BOTTOM w0.5: R7.1@66.5,47.6 R3.2@66.5,49.4
N15966322: IC22.3 R79.1 | length 1.4
  TOP w0.2: R79.1@141.5,151 142.875,151 IC22.3@142.925,151.05
N15969728: DS1.A R145.2 | length 1.2
  TOP w0.5: DS1.A@120.75,158.075 R145.2@120.75,159.25
N15969732: DS2.A R146.2 | length 1.2
  TOP w0.5: DS2.A@119.25,158.075 R146.2@119.25,159.25
N15969736: DS3.A R147.2 | length 1.2
  TOP w0.5: DS3.A@117.75,158.075 R147.2@117.75,159.25
N15969740: DS4.A R148.2 | length 1.2
  TOP w0.5: DS4.A@116.25,158.075 R148.2@116.25,159.25
N15970009: R149.2 R210.1 S1.1 | length 9.4
  TOP w0.2: R149.2@109.095,146.65 S1.1@109.095,147.94 109.095,149.05 110.295,150.25 113.85,150.25 R210.1@115.1,151.5
N15970013: R150.2 R211.1 S1.2 | length 7.7
  TOP w0.2: R150.2@110.365,146.65 S1.2@110.365,147.94 110.365,149.05 111.165,149.85 114.5,149.85 R211.1@115.1,150.45
N15970017: R151.2 R212.1 S1.3 | length 6
  TOP w0.2: R151.2@111.635,146.65 S1.3@111.635,147.94 111.635,149.05 112.035,149.45 R212.1@115.1,149.45
N15970021: R152.2 R213.1 S1.4 | length 4.7
  TOP w0.2: R152.2@112.905,146.65 S1.4@112.905,147.94 112.905,148.805 113.15,149.05 114.5,149.05 R213.1@115.1,148.45
N15981855: C102.1 R153.2 R209.1 S2.1 S2.2 | length 12.6
  TOP w0.2: R209.1@146.2,134.5 R153.2@147.2,134.5 148.45,134.5 C102.1@148.5,134.45 150.1,134.45 S2.2@150.3,134.25
  TOP w0.6: S2.2@150.3,134.25 S2.1@158.7,134.25
N16080427: Q2.4 R154.2 R208.1 | length 3.4
  BOTTOM w0.4: Q2.4@208.475,38.8 210.05,38.8 R208.1@210.25,38.6
  BOTTOM w0.8: R208.1@210.25,38.6 210.3,38.65 R154.2@211.75,38.65
N16084254: CN3.3 pad.@189.55,168.4 R160.2 | length 2.3
  TOP w0.2: CN3.3@189.545,167.075 189.545,167.95 pad.@189.55,168.4
  BOTTOM w0.2: R160.2@189.55,167.45 pad.@189.55,168.4
N16084299: CN3.5 pad.@188.25,168.4 R161.2 | length 2.3
  TOP w0.2: pad.@188.25,168.4 188.275,167.951 CN3.5@188.275,167.075
  BOTTOM w0.2: R161.2@188.25,167.45 pad.@188.25,168.4
N16084344: CN3.9 pad.@185.75,168.4 R162.2 | length 2.3
  TOP w0.2: CN3.9@185.735,167.075 185.735,167.95 pad.@185.75,168.4
  BOTTOM w0.2: R162.2@185.75,167.45 pad.@185.75,168.4
N16084389: CN3.11 pad.@184.45,168.4 R163.2 | length 2.3
  TOP w0.2: pad.@184.45,168.4 184.465,167.95 CN3.11@184.465,167.075
  BOTTOM w0.2: R163.2@184.45,167.45 pad.@184.45,168.4
N16084434: CN3.13 pad.@183.2,168.4 R164.2 | length 2.3
  TOP w0.2: CN3.13@183.195,167.075 183.195,167.95 pad.@183.2,168.4
  BOTTOM w0.2: R164.2@183.2,167.45 pad.@183.2,168.4
N16084479: CN3.19 pad.@179.4,168.4 R165.2 | length 2.3
  TOP w0.2: CN3.19@179.385,167.075 179.385,167.95 pad.@179.4,168.4
  BOTTOM w0.2: R165.2@179.4,167.45 pad.@179.4,168.4
N16084524: CN3.21 pad.@178.1,168.4 R166.2 | length 2.3
  TOP w0.2: pad.@178.1,168.4 178.115,167.95 CN3.21@178.115,167.075
  BOTTOM w0.2: R166.2@178.1,167.45 pad.@178.1,168.4
N16084569: CN3.23 pad.@176.85,168.4 R167.2 | length 2.3
  TOP w0.2: CN3.23@176.845,167.075 176.845,167.95 pad.@176.85,168.4
  BOTTOM w0.2: R167.2@176.85,167.45 pad.@176.85,168.4
N16128748: D2.1 D2.2 T3.8 T3.9
N16129695: D4.K D6.K
N16132048: CN3.6 R198.1 | length 1.5
  TOP w0.2: R198.1@188.275,162.7 CN3.6@188.275,164.205
N16289804: C128.2 R197.1 | length 1.3
  BOTTOM w0.8: C128.2@210.1,32 R197.1@211.4,32
N16355511: C5.2 R4.1 | length 1.3
  TOP w0.3: R4.1@66.35,33.25 C5.2@67.65,33.25
N16465335: IC4.3 R36.2 | length 2.5
  TOP w0.2: R36.2@105.4,140.25 105.4,139.1 105.8,138.7 IC4.3@106.55,138.7
N16465385: IC5.3 R39.2 | length 2.5
  TOP w0.2: R39.2@95.9,140.25 95.9,139.1 96.3,138.7 IC5.3@97.05,138.7
N16663040: CN3.8 R238.1 | length 1.5
  TOP w0.2: R238.1@187.005,162.7 CN3.8@187.005,164.205
N16663424: CN3.22 R239.1 | length 1.5
  TOP w0.2: R239.1@178.115,162.715 CN3.22@178.115,164.205
N16663428: CN3.24 R240.1 | length 1.5
  TOP w0.2: R240.1@176.845,162.705 CN3.24@176.845,164.205
N16677268: D50.A R245.1 | length 1.4
  TOP w0.6: D50.A@74.9,159.25 74.9,157.95 R245.1@75,157.85
N16677456: D51.A R246.1 | length 1.4
  TOP w0.6: D51.A@74.9,150 74.9,148.7 R246.1@75,148.6
N16677751: D52.A R247.1 | length 1.4
  TOP w0.6: D52.A@74.9,140.75 74.9,139.45 R247.1@75,139.35
N16678100: D53.A R249.1 | length 1.4
  TOP w0.6: D53.A@74.9,131.5 74.9,130.2 R249.1@75,130.1
N16678365: D54.A R251.1 | length 1.4
  TOP w0.6: D54.A@74.9,118.65 74.9,117.35 R251.1@75,117.25
N16678572: D55.A R253.1 | length 1.4
  TOP w0.6: D55.A@74.9,109.4 74.9,108.1 R253.1@75,108
N16678779: D56.A R255.1 | length 1.4
  TOP w0.6: D56.A@74.9,100.15 74.9,98.85 R255.1@75,98.75
N16678984: D57.A R257.1 | length 1.4
  TOP w0.6: D57.A@74.9,90.9 74.9,89.6 R257.1@75,89.5
N16682431: D58.A R258.1 | length 1.4
  TOP w0.6: D58.A@104.75,114.15 106.05,114.15 R258.1@106.15,114.25
N16682896: D59.A R260.1 | length 1.4
  TOP w0.6: D59.A@114,114.15 115.3,114.15 R260.1@115.4,114.25
N16683103: D60.A R262.1 | length 1.4
  TOP w0.6: D60.A@123.25,114.15 124.55,114.15 R262.1@124.65,114.25
N16683312: D61.A R264.1 | length 1.4
  TOP w0.6: D61.A@145.35,114.15 146.65,114.15 R264.1@146.75,114.25
N16683534: D62.A R266.1 | length 1.4
  TOP w0.6: D62.A@132.5,114.15 133.8,114.15 R266.1@133.9,114.25
N16683743: D63.A R268.1 | length 1.4
  TOP w0.6: D63.A@154.6,114.15 155.9,114.15 R268.1@156,114.25
N16683946: D64.A R270.1 | length 1.4
  TOP w0.6: D64.A@163.85,114.15 165.15,114.15 R270.1@165.25,114.25
N16684168: D65.A R272.1 | length 1.4
  TOP w0.6: D65.A@173.1,114.15 174.4,114.15 R272.1@174.5,114.25
N16689205: D66.A R274.1 | length 1.4
  TOP w0.6: R274.1@209,85.3 209.1,85.2 D66.A@209.1,83.9
N16689414: D67.A R276.1 | length 1.4
  TOP w0.6: R276.1@209,94.55 209.1,94.45 D67.A@209.1,93.15
N16689619: D68.A R278.1 | length 1.4
  TOP w0.6: R278.1@209,103.8 209.1,103.7 D68.A@209.1,102.4
N16689826: D69.A R280.1 | length 1.4
  TOP w0.6: R280.1@209,113.05 209.1,112.95 D69.A@209.1,111.65
N16690061: D70.A R282.1 | length 1.4
  TOP w0.6: R282.1@209,125.9 209.1,125.8 D70.A@209.1,124.5
N16690281: D71.A R284.1 | length 1.4
  TOP w0.6: R284.1@209,135.15 209.1,135.05 D71.A@209.1,133.75
N16690501: D72.A R286.1 | length 1.4
  TOP w0.6: R286.1@209,144.4 209.1,144.3 D72.A@209.1,143
N16690719: D73.A R288.1 | length 1.4
  TOP w0.6: R288.1@209,153.65 209.1,153.55 D73.A@209.1,152.25
N16776249: IC11.6 R291.1 R292.2 | length 3.3
  TOP w0.2: IC11.6@183.5,124.182 R292.2@183.5,126.5 R291.1@183.5,127.5
N16781117: IC2.15 R295.2 | length 1.4
  TOP w0.3: R295.2@173.1,52.6 173.125,52.625 IC2.15@174.513,52.625
N16783087: R24.1 R27.1 | length 1
  TOP w0.3: R27.1@183.7,53.5 R24.1@184.7,53.5
N16783507: IC2.4 pad.@181.8,53.925 R297.1 | length 2.2
  TOP w0.2: IC2.4@180.488,53.925 pad.@181.8,53.925
  BOTTOM w0.3: pad.@181.8,53.925 182.675,53.925 R297.1@182.7,53.95
N17104568: D1.2 R2.2 | length 1.4
  TOP w0.3: R2.2@64.95,31.35 D1.2@66.4,31.35
N159286810: C12.1 R14.2 | length 1.2
  TOP w0.5: R14.2@75.35,34.75 C12.1@76.5,34.75
N159479370: R28.2 R29.1 | length 1.5
  BOTTOM w0.8: R28.2@214.2,41 R29.1@214.2,42.5
OC_U: IC14.7 IC17.1 | length 4.3
  TOP w0.2: IC17.1@178.85,139 179.5,139 179.6,138.9 181.55,138.9 182.15,139.5 IC14.7@182.9,139.5
OC_U_N: IC13.7 IC14.2 | length 9
  TOP w0.2: IC13.7@184.9,144.5 184.4,144.5 184.25,144.35 184.25,141.75 184.75,141.25 186.25,141.25 187.15,140.35 187.15,139.85 186.8,139.5 IC14.2@185.6,139.5
OC_U_P: IC13.1 IC14.1 | length 6.6
  TOP w0.2: IC14.1@185.6,139 186.9,139 187.6,139.7 IC13.1@187.6,144
OC_UV: IC16.1 IC17.7 | length 4.3
  TOP w0.2: IC16.1@172.1,139 172.7,139 172.8,138.9 173.35,138.9 173.95,139.5 IC17.7@176.15,139.5
OC_V: IC14.3 IC17.2 pad.@180.6,139.5 pad.@186.55,140.1 | length 8.9
  TOP w0.2: IC17.2@178.85,139.5 pad.@180.6,139.5 ; IC14.3@185.6,140 186.111,140 pad.@186.55,140.1
  BOTTOM w0.2: pad.@180.6,139.5 185.95,139.5 pad.@186.55,140.1
OC_V_N: IC14.6 IC15.7 | length 10.4
  TOP w0.2: IC15.7@177.15,144.5 176.65,144.5 176.5,144.35 176.5,141.75 177,141.25 179.7,141.25 180.95,140 IC14.6@182.9,140
OC_V_P: IC14.5 IC15.1 | length 5.8
  TOP w0.2: IC15.1@179.85,144 179.85,141.7 181.05,140.5 IC14.5@182.9,140.5
OC_W: IC16.2 IC17.3 pad.@173.05,139.5 pad.@179.8,140.1 | length 8.9
  TOP w0.2: IC16.2@172.1,139.5 pad.@173.05,139.5 ; IC17.3@178.85,140 179.361,140 pad.@179.8,140.1
  BOTTOM w0.2: pad.@173.05,139.5 179.2,139.5 pad.@179.8,140.1
OC_W_N: IC17.6 IC18.7 | length 11.4
  TOP w0.2: IC18.7@169.4,144.5 168.9,144.5 168.75,144.35 168.75,141.75 169.25,141.25 172.95,141.25 174.2,140 IC17.6@176.15,140
OC_W_P: IC17.5 IC18.1 | length 6.3
  TOP w0.2: IC18.1@172.1,144 172.1,142.7 174.3,140.5 IC17.5@176.15,140.5
OSC_ST_N: C46.1 IC22.1 IC22.4 R74.2 | length 6
  TOP w0.2: IC22.4@142.925,148.95 142.925,147.975 143.05,147.85 144.25,147.85 144.575,148.175 IC22.1@144.575,148.95
  TOP w0.5: R74.2@141.5,150 C46.1@141.5,149 142.875,149 IC22.4@142.925,148.95
OUT_U: CN5.1 DR1.1 pad.@51,119.45 pad.@51,120.65 pad.@51,121.85 pad.@51,123.05 pad.@51,124.25 pad.@51,125.45 pad.@52.2,119.45 pad.@52.2,120.65 pad.@52.2,121.85 pad.@52.2,123.05 pad.@52.2,124.25 pad.@52.2,125.45 pad.@53.4,119.45 pad.@53.4,120.65 pad.@53.4,121.85 pad.@53.4,123.05 pad.@53.4,124.25 pad.@53.4,125.45 pad.@54.6,119.45 pad.@54.6,120.65 pad.@54.6,121.85 pad.@54.6,123.05 pad.@54.6,124.25 pad.@54.6,125.45 pad.@55.8,119.45 pad.@55.8,120.65 pad.@55.8,121.85 pad.@55.8,123.05 pad.@55.8,124.25 pad.@55.8,125.45 pad.@57,119.45 pad.@57,120.65 pad.@57,121.85 pad.@57,123.05 pad.@57,124.25 pad.@57,125.45 pad.@58.2,119.45 pad.@58.2,120.65 pad.@58.2,121.85 pad.@58.2,123.05 pad.@58.2,124.25 pad.@58.2,125.45
OUT_V: CN5.2 DR2.1 pad.@138.55,90.25 pad.@138.55,91.45 pad.@138.55,92.65 pad.@138.55,93.85 pad.@138.55,95.05 pad.@138.55,96.25 pad.@138.55,97.45 pad.@139.75,90.25 pad.@139.75,91.45 pad.@139.75,92.65 pad.@139.75,93.85 pad.@139.75,95.05 pad.@139.75,96.25 pad.@139.75,97.45 pad.@140.95,90.25 pad.@140.95,91.45 pad.@140.95,92.65 pad.@140.95,93.85 pad.@140.95,95.05 pad.@140.95,96.25 pad.@140.95,97.45 pad.@142.15,90.25 pad.@142.15,91.45 pad.@142.15,92.65 pad.@142.15,93.85 pad.@142.15,95.05 pad.@142.15,96.25 pad.@142.15,97.45 pad.@143.35,90.25 pad.@143.35,91.45 pad.@143.35,92.65 pad.@143.35,93.85 pad.@143.35,95.05 pad.@143.35,96.25 pad.@143.35,97.45 pad.@144.55,90.25 pad.@144.55,91.45 pad.@144.55,92.65 pad.@144.55,93.85 pad.@144.55,95.05 pad.@144.55,96.25 pad.@144.55,97.45
OUT_W: CN5.3 DR3.1 pad.@225.8,117.7 pad.@225.8,118.9 pad.@225.8,120.1 pad.@225.8,121.3 pad.@225.8,122.5 pad.@225.8,123.7 pad.@227,117.7 pad.@227,118.9 pad.@227,120.1 pad.@227,121.3 pad.@227,122.5 pad.@227,123.7 pad.@228.2,117.7 pad.@228.2,118.9 pad.@228.2,120.1 pad.@228.2,121.3 pad.@228.2,122.5 pad.@228.2,123.7 pad.@229.4,117.7 pad.@229.4,118.9 pad.@229.4,120.1 pad.@229.4,121.3 pad.@229.4,122.5 pad.@229.4,123.7 pad.@230.6,117.7 pad.@230.6,118.9 pad.@230.6,120.1 pad.@230.6,121.3 pad.@230.6,122.5 pad.@230.6,123.7 pad.@231.8,117.7 pad.@231.8,118.9 pad.@231.8,120.1 pad.@231.8,121.3 pad.@231.8,122.5 pad.@231.8,123.7 pad.@233,117.7 pad.@233,118.9 pad.@233,120.1 pad.@233,121.3 pad.@233,122.5 pad.@233,123.7
PC_ANODE_U1: C142.1 PC1.1 R81.2 R337.1 | length 3.4
  BOTTOM w0.2: PC1.1@85.6,159.02 85.62,159 R337.1@87,159 C142.1@88,159 R81.2@88,159.95
PC_ANODE_U2: C143.1 PC2.1 R83.2 R338.1 | length 3.4
  BOTTOM w0.2: PC2.1@85.6,149.77 85.62,149.75 R338.1@87,149.75 C143.1@88,149.75 R83.2@88,150.7
PC_ANODE_U3: C144.1 PC3.1 R85.2 R339.1 | length 3.4
  BOTTOM w0.2: PC3.1@85.6,140.52 85.62,140.5 R339.1@87,140.5 C144.1@88,140.5 R85.2@88,141.45
PC_ANODE_U4: C145.1 PC4.1 R87.2 R340.1 | length 3.4
  BOTTOM w0.2: PC4.1@85.6,131.27 85.62,131.25 R340.1@87,131.25 C145.1@88,131.25 R87.2@88,132.2
PC_ANODE_U5: C146.1 PC5.1 R89.2 R341.1 | length 3.3
  BOTTOM w0.2: PC5.1@85.6,118.42 85.67,118.35 R341.1@86.95,118.35 C146.1@87.95,118.35 R89.2@87.95,119.3
PC_ANODE_U6: C147.1 PC6.1 R91.2 R342.1 | length 3.3
  BOTTOM w0.2: PC6.1@85.6,109.17 85.67,109.1 R342.1@86.95,109.1 C147.1@87.95,109.1 R91.2@87.95,110.05
PC_ANODE_U7: C148.1 PC7.1 R93.2 R343.1 | length 3.3
  BOTTOM w0.2: PC7.1@85.6,99.92 85.67,99.85 R343.1@86.95,99.85 C148.1@87.95,99.85 R93.2@87.95,100.8
PC_ANODE_U8: C149.1 PC8.1 R95.2 R344.1 | length 3.3
  BOTTOM w0.2: PC8.1@85.6,90.67 85.67,90.6 R344.1@86.95,90.6 C149.1@87.95,90.6 R95.2@87.95,91.55
PC_ANODE_V1: C150.1 PC9.1 R97.2 R345.1 | length 3.4
  BOTTOM w0.2: R97.2@104.05,127.25 C150.1@105,127.25 R345.1@105,126.25 105,124.87 PC9.1@104.98,124.85
PC_ANODE_V2: C151.1 PC10.1 R99.2 R346.1 | length 3.4
  BOTTOM w0.2: R99.2@113.3,127.25 C151.1@114.25,127.25 R346.1@114.25,126.25 114.25,124.87 PC10.1@114.23,124.85
PC_ANODE_V3: C152.1 PC11.1 R100.2 R347.1 | length 3.4
  BOTTOM w0.2: R100.2@122.55,127.25 C152.1@123.5,127.25 R347.1@123.5,126.25 123.5,124.87 PC11.1@123.48,124.85
PC_ANODE_V4: C153.1 PC12.1 R102.2 R348.1 | length 3.4
  BOTTOM w0.2: R102.2@131.8,127.25 C153.1@132.75,127.25 R348.1@132.75,126.25 132.75,124.87 PC12.1@132.73,124.85
PC_ANODE_V5: C154.1 PC13.1 R105.2 R349.1 | length 4.5
  BOTTOM w0.2: PC13.1@145.58,124.85 145.58,125.68 146.15,126.25 R349.1@147.15,126.25 C154.1@147.15,127.25 R105.2@146.25,127.25
PC_ANODE_V6: C155.1 PC14.1 R107.2 R350.1 | length 4.5
  BOTTOM w0.2: PC14.1@154.83,124.85 154.83,125.68 155.4,126.25 R350.1@156.4,126.25 C155.1@156.4,127.25 R107.2@155.5,127.25
PC_ANODE_V7: C156.1 PC15.1 R109.2 R351.1 | length 4.5
  BOTTOM w0.2: PC15.1@164.08,124.85 164.08,125.68 164.65,126.25 R351.1@165.65,126.25 C156.1@165.65,127.25 R109.2@164.75,127.25
PC_ANODE_V8: C157.1 PC16.1 R111.2 R352.1 | length 4.5
  BOTTOM w0.2: PC16.1@173.33,124.85 173.33,125.68 173.9,126.25 R352.1@174.9,126.25 C157.1@174.9,127.25 R111.2@174,127.25
PC_ANODE_W1: C158.1 PC17.1 R113.2 R353.1 | length 4.6
  BOTTOM w0.2: R113.2@196,85 C158.1@196,85.9 R353.1@197,85.9 197,84.9 197.6,84.3 198.23,84.3 PC17.1@198.4,84.13
PC_ANODE_W2: C159.1 PC18.1 R115.2 R354.1 | length 4.6
  BOTTOM w0.2: R115.2@196,94.25 C159.1@196,95.15 R354.1@197,95.15 197,94.1 197.55,93.55 198.23,93.55 PC18.1@198.4,93.38
PC_ANODE_W3: C160.1 PC19.1 R117.2 R355.1 | length 4.6
  BOTTOM w0.2: R117.2@196,103.5 C160.1@196,104.4 R355.1@197,104.4 197,103.35 197.55,102.8 198.23,102.8 PC19.1@198.4,102.63
PC_ANODE_W4: C161.1 PC20.1 R119.2 R356.1 | length 4.6
  BOTTOM w0.2: R119.2@196,112.75 C161.1@196,113.65 R356.1@197,113.65 197,112.6 197.55,112.05 198.23,112.05 PC20.1@198.4,111.88
PC_ANODE_W5: C162.1 PC21.1 R121.2 R357.1 | length 3.4
  BOTTOM w0.2: R121.2@196,123.8 C162.1@196,124.75 R357.1@197,124.75 198.38,124.75 PC21.1@198.4,124.73
PC_ANODE_W6: C163.1 PC22.1 R123.2 R358.1 | length 3.4
  BOTTOM w0.2: R123.2@196,133.05 C163.1@196,134 R358.1@197,134 198.38,134 PC22.1@198.4,133.98
PC_ANODE_W7: C164.1 PC23.1 R125.2 R359.1 | length 3.4
  BOTTOM w0.2: R125.2@196,142.3 C164.1@196,143.25 R359.1@197,143.25 198.38,143.25 PC23.1@198.4,143.23
PC_ANODE_W8: C165.1 PC24.1 R127.2 R360.1 | length 3.4
  BOTTOM w0.2: R127.2@196,151.55 C165.1@196,152.5 R360.1@197,152.5 198.38,152.5 PC24.1@198.4,152.48
PC_G_U1: C47.2 C112.2 D15.5 PC1.4 Q3.1 Q3.2 Q3.3 Q5.5 Q5.6 Q5.7 Q5.8 R214.2 TP65.1 | length 14.7
  TOP w0.5: 75,152.95 R214.2@75,154
  TOP w1: 72,152.95 75,152.95 77.2,152.95 TP65.1@79,154.75
  BOTTOM w0.6: C112.2@76.75,156.9 77.17,156.48 PC1.4@78.9,156.48 79,156.38 TP65.1@79,154.75
  BOTTOM w0.8: C47.2@75,156.775 75.125,156.9 C112.2@76.75,156.9
PC_G_U2: C50.2 C113.2 D17.5 PC2.4 Q5.1 Q5.2 Q5.3 Q7.5 Q7.6 Q7.7 Q7.8 R215.2 TP66.1 | length 14.7
  TOP w0.5: 75,143.7 R215.2@75,144.75
  TOP w1: 72,143.7 75,143.7 77.2,143.7 TP66.1@79,145.5
  BOTTOM w0.6: C113.2@76.75,147.65 77.17,147.23 PC2.4@78.9,147.23 79,147.13 TP66.1@79,145.5
  BOTTOM w0.8: C50.2@75,147.525 75.125,147.65 C113.2@76.75,147.65
PC_G_U3: C53.2 C114.2 D19.5 PC3.4 Q7.1 Q7.2 Q7.3 Q9.5 Q9.6 Q9.7 Q9.8 R216.2 TP67.1 | length 14.7
  TOP w0.5: 75,134.45 R216.2@75,135.5
  TOP w1: 72,134.45 75,134.45 77.2,134.45 TP67.1@79,136.25
  BOTTOM w0.6: C114.2@76.75,138.4 77.17,137.98 PC3.4@78.9,137.98 79,137.88 TP67.1@79,136.25
  BOTTOM w0.8: C53.2@75,138.275 75.125,138.4 C114.2@76.75,138.4
PC_G_U5: C57.2 C116.2 D21.3 D21.4 PC5.4 Q11.1 Q11.2 Q11.3 Q13.5 Q13.6 Q13.7 Q13.8 R218.2 TP69.1 | length 14.7
  TOP w0.5: 75,112.35 R218.2@75,113.4
  TOP w1: 72,112.35 75,112.35 77.2,112.35 TP69.1@79,114.15
  BOTTOM w0.6: C116.2@76.75,116.3 77.17,115.88 PC5.4@78.9,115.88 79,115.78 TP69.1@79,114.15
  BOTTOM w0.8: C57.2@75,116.175 75.125,116.3 C116.2@76.75,116.3
PC_G_U6: C58.2 C117.2 D23.3 D23.4 PC6.4 Q13.1 Q13.2 Q13.3 Q15.5 Q15.6 Q15.7 Q15.8 R219.2 TP70.1 | length 14.7
  TOP w0.5: 75,103.1 R219.2@75,104.15
  TOP w1: 72,103.1 75,103.1 77.2,103.1 TP70.1@79,104.9
  BOTTOM w0.6: C117.2@76.75,107.05 77.17,106.63 PC6.4@78.9,106.63 79,106.53 TP70.1@79,104.9
  BOTTOM w0.8: C58.2@75,106.925 75.125,107.05 C117.2@76.75,107.05
PC_G_U7: C59.2 C118.2 D25.3 D25.4 PC7.4 Q15.1 Q15.2 Q15.3 Q17.5 Q17.6 Q17.7 Q17.8 R220.2 TP71.1 | length 14.7
  TOP w0.5: 75,93.85 R220.2@75,94.9
  TOP w1: 72,93.85 75,93.85 75.85,93.85 77.65,95.65 TP71.1@79,95.65
  BOTTOM w0.6: C118.2@76.75,97.8 77.17,97.38 PC7.4@78.9,97.38 79,97.28 TP71.1@79,95.65
  BOTTOM w0.8: C59.2@75,97.675 75.125,97.8 C118.2@76.75,97.8
PC_G_U8: C60.2 C119.2 IC10.1 IC10.2 PC8.4 Q17.1 Q17.2 Q17.3 R221.2 TP72.1 | length 15.7
  TOP w0.5: 75,84.6 R221.2@75,85.65
  TOP w1: 72,84.6 75,84.6 79,84.6 TP72.1@79,86.4
  BOTTOM w0.6: C119.2@76.75,88.55 77.17,88.13 PC8.4@78.9,88.13 79,88.03 TP72.1@79,86.4
  BOTTOM w0.8: C60.2@75,88.425 75.125,88.55 C119.2@76.75,88.55
PC_G_V1: C62.2 C104.2 D27.5 PC9.4 Q19.1 Q19.2 Q19.3 Q21.5 Q21.6 Q21.7 Q21.8 R222.2 TP73.1 | length 14.7
  TOP w0.5: R222.2@110,114.25 111.05,114.25
  TOP w1: TP73.1@109.25,118.25 111.05,116.45 111.05,114.25 111.05,111.25
  BOTTOM w0.6: C104.2@107.1,116 107.52,116.42 PC9.4@107.52,118.15 107.62,118.25 TP73.1@109.25,118.25
  BOTTOM w0.8: C104.2@107.1,116 107.1,114.375 C62.2@107.225,114.25
PC_G_V2: C64.2 C105.2 D29.5 PC10.4 Q21.1 Q21.2 Q21.3 Q23.5 Q23.6 Q23.7 Q23.8 R223.2 TP74.1 | length 14.7
  TOP w0.5: R223.2@119.25,114.25 120.3,114.25
  TOP w1: TP74.1@118.5,118.25 120.3,116.45 120.3,114.25 120.3,111.25
  BOTTOM w0.6: C105.2@116.35,116 116.77,116.42 PC10.4@116.77,118.15 116.87,118.25 TP74.1@118.5,118.25
  BOTTOM w0.8: C105.2@116.35,116 116.35,114.375 C64.2@116.475,114.25
PC_G_V3: C68.2 C106.2 D31.5 PC11.4 Q23.1 Q23.2 Q23.3 Q25.5 Q25.6 Q25.7 Q25.8 R224.2 TP75.1 | length 14.7
  TOP w0.5: R224.2@128.5,114.25 129.55,114.25
  TOP w1: TP75.1@127.75,118.25 129.55,116.45 129.55,114.25 129.55,111.25
  BOTTOM w0.6: C106.2@125.6,116 126.02,116.42 PC11.4@126.02,118.15 126.12,118.25 TP75.1@127.75,118.25
  BOTTOM w0.8: C106.2@125.6,116 125.6,114.375 C68.2@125.725,114.25
PC_G_V5: C72.2 C108.2 D33.3 D33.4 PC13.4 Q27.1 Q27.2 Q27.3 Q29.5 Q29.6 Q29.7 Q29.8 R226.2 TP77.1 | length 14.7
  TOP w0.5: R226.2@150.6,114.25 151.65,114.25
  TOP w1: TP77.1@149.85,118.25 151.65,116.45 151.65,114.25 151.65,111.25
  BOTTOM w0.6: C108.2@147.7,116 148.12,116.42 PC13.4@148.12,118.15 148.22,118.25 TP77.1@149.85,118.25
  BOTTOM w0.8: C108.2@147.7,116 147.7,114.375 C72.2@147.825,114.25
PC_G_V6: C73.2 C109.2 D35.3 D35.4 PC14.4 Q29.1 Q29.2 Q29.3 Q31.5 Q31.6 Q31.7 Q31.8 R227.2 TP78.1 | length 14.7
  TOP w0.5: R227.2@159.85,114.25 160.9,114.25
  TOP w1: TP78.1@159.1,118.25 160.9,116.45 160.9,114.25 160.9,111.25
  BOTTOM w0.6: C109.2@156.95,116 157.37,116.42 PC14.4@157.37,118.15 157.47,118.25 TP78.1@159.1,118.25
  BOTTOM w0.8: C109.2@156.95,116 156.95,114.375 C73.2@157.075,114.25
PC_G_V7: C74.2 C110.2 D37.3 D37.4 PC15.4 Q31.1 Q31.2 Q31.3 Q33.5 Q33.6 Q33.7 Q33.8 R228.2 TP79.1 | length 14.7
  TOP w0.5: R228.2@169.1,114.25 170.15,114.25
  TOP w1: TP79.1@168.35,118.25 168.35,116.9 170.15,115.1 170.15,114.25 170.15,111.25
  BOTTOM w0.6: C110.2@166.2,116 166.62,116.42 PC15.4@166.62,118.15 166.72,118.25 TP79.1@168.35,118.25
  BOTTOM w0.8: C110.2@166.2,116 166.2,114.375 C74.2@166.325,114.25
PC_G_V8: C76.2 C111.2 IC11.1 IC11.2 PC16.4 Q33.1 Q33.2 Q33.3 R229.2 TP80.1 | length 15.7
  TOP w0.5: R229.2@178.35,114.25 179.4,114.25
  TOP w1: TP80.1@177.6,118.25 179.4,118.25 179.4,114.25 179.4,111.25
  BOTTOM w0.6: C111.2@175.45,116 175.87,116.42 PC16.4@175.87,118.15 175.97,118.25 TP80.1@177.6,118.25
  BOTTOM w0.8: C111.2@175.45,116 175.45,114.375 C76.2@175.575,114.25
PC_G_W1: C77.2 C120.2 D39.5 PC17.4 Q35.1 Q35.2 Q35.3 Q37.5 Q37.6 Q37.7 Q37.8 R230.2 TP81.1 | length 14.7
  TOP w0.5: R230.2@209,89.15 209,90.2
  TOP w1: TP81.1@205,88.4 206.8,90.2 209,90.2 212,90.2
  BOTTOM w0.6: TP81.1@205,88.4 205,86.77 PC17.4@205.1,86.67 206.83,86.67 C120.2@207.25,86.25
  BOTTOM w0.8: C120.2@207.25,86.25 208.875,86.25 C77.2@209,86.375
PC_G_W2: C79.2 C121.2 D41.5 PC18.4 Q37.1 Q37.2 Q37.3 Q39.5 Q39.6 Q39.7 Q39.8 R231.2 TP82.1 | length 14.7
  TOP w0.5: R231.2@209,98.4 209,99.45
  TOP w1: TP82.1@205,97.65 206.8,99.45 209,99.45 212,99.45
  BOTTOM w0.6: TP82.1@205,97.65 205,96.02 PC18.4@205.1,95.92 206.83,95.92 C121.2@207.25,95.5
  BOTTOM w0.8: C121.2@207.25,95.5 208.875,95.5 C79.2@209,95.625
PC_G_W3: C81.2 C122.2 D43.5 PC19.4 Q39.1 Q39.2 Q39.3 Q41.5 Q41.6 Q41.7 Q41.8 R232.2 TP83.1 | length 14.7
  TOP w0.5: R232.2@209,107.65 209,108.7
  TOP w1: TP83.1@205,106.9 206.8,108.7 209,108.7 212,108.7
  BOTTOM w0.6: TP83.1@205,106.9 205,105.27 PC19.4@205.1,105.17 206.83,105.17 C122.2@207.25,104.75
  BOTTOM w0.8: C122.2@207.25,104.75 208.875,104.75 C81.2@209,104.875
PC_G_W5: C85.2 C124.2 D45.3 D45.4 PC21.4 Q43.1 Q43.2 Q43.3 Q45.5 Q45.6 Q45.7 Q45.8 R234.2 TP85.1 | length 14.7
  TOP w0.5: R234.2@209,129.75 209,130.8
  TOP w1: TP85.1@205,129 206.8,130.8 209,130.8 212,130.8
  BOTTOM w0.6: TP85.1@205,129 205,127.37 PC21.4@205.1,127.27 206.83,127.27 C124.2@207.25,126.85
  BOTTOM w0.8: C124.2@207.25,126.85 208.875,126.85 C85.2@209,126.975
PC_G_W6: C86.2 C125.2 D47.3 D47.4 PC22.4 Q45.1 Q45.2 Q45.3 Q47.5 Q47.6 Q47.7 Q47.8 R235.2 TP86.1 | length 14.7
  TOP w0.5: R235.2@209,139 209,140.05
  TOP w1: TP86.1@205,138.25 206.8,140.05 209,140.05 212,140.05
  BOTTOM w0.6: TP86.1@205,138.25 205,136.62 PC22.4@205.1,136.52 206.83,136.52 C125.2@207.25,136.1
  BOTTOM w0.8: C125.2@207.25,136.1 208.875,136.1 C86.2@209,136.225
PC_G_W7: C87.2 C126.2 D49.3 D49.4 PC23.4 Q47.1 Q47.2 Q47.3 Q49.5 Q49.6 Q49.7 Q49.8 R236.2 TP87.1 | length 14.7
  TOP w0.5: R236.2@209,148.25 209,149.3
  TOP w1: TP87.1@205,147.5 206.8,149.3 209,149.3 212,149.3
  BOTTOM w0.6: TP87.1@205,147.5 205,145.87 PC23.4@205.1,145.77 206.83,145.77 C126.2@207.25,145.35
  BOTTOM w0.8: C126.2@207.25,145.35 208.875,145.35 C87.2@209,145.475
PC_G_W8: C88.2 C127.2 IC12.1 IC12.2 PC24.4 Q49.1 Q49.2 Q49.3 R237.2 TP88.1 | length 15.7
  TOP w0.5: R237.2@209,157.5 209,158.55
  TOP w1: TP88.1@205,156.75 205,158.55 209,158.55 212,158.55
  BOTTOM w0.6: TP88.1@205,156.75 205,155.12 PC24.4@205.1,155.02 206.83,155.02 C127.2@207.25,154.6
  BOTTOM w0.8: C127.2@207.25,154.6 208.875,154.6 C88.2@209,154.725
PC_GD_U1: D50.K pad.@77.6,157.75 PC1.5 R176.1 | length 3.9
  TOP w0.6: D50.K@76.6,159.25 76.6,157.95 R176.1@76.5,157.85 76.6,157.75 pad.@77.6,157.75
  BOTTOM w0.6: pad.@77.6,157.75 PC1.5@78.9,157.75
PC_GD_U2: D51.K pad.@77.6,148.5 PC2.5 R177.1 | length 3.9
  TOP w0.6: D51.K@76.6,150 76.6,148.7 R177.1@76.5,148.6 76.6,148.5 pad.@77.6,148.5
  BOTTOM w0.6: pad.@77.6,148.5 PC2.5@78.9,148.5
PC_GD_U3: D52.K pad.@77.6,139.25 PC3.5 R178.1 | length 3.9
  TOP w0.6: D52.K@76.6,140.75 76.6,139.45 R178.1@76.5,139.35 76.6,139.25 pad.@77.6,139.25
  BOTTOM w0.6: pad.@77.6,139.25 PC3.5@78.9,139.25
PC_GD_U4: D53.K pad.@77.6,130 PC4.5 R179.1 | length 3.9
  TOP w0.6: D53.K@76.6,131.5 76.6,130.2 R179.1@76.5,130.1 76.6,130 pad.@77.6,130
  BOTTOM w0.6: pad.@77.6,130 PC4.5@78.9,130
PC_GD_U5: D54.K pad.@77.6,117.15 PC5.5 R180.1 | length 3.9
  TOP w0.6: D54.K@76.6,118.65 76.6,117.35 R180.1@76.5,117.25 76.6,117.15 pad.@77.6,117.15
  BOTTOM w0.6: pad.@77.6,117.15 PC5.5@78.9,117.15
PC_GD_U6: D55.K pad.@77.6,107.9 PC6.5 R181.1 | length 3.9
  TOP w0.6: D55.K@76.6,109.4 76.6,108.1 R181.1@76.5,108 76.6,107.9 pad.@77.6,107.9
  BOTTOM w0.6: pad.@77.6,107.9 PC6.5@78.9,107.9
PC_GD_U7: D56.K pad.@77.6,98.65 PC7.5 R182.1 | length 3.9
  TOP w0.6: D56.K@76.6,100.15 76.6,98.85 R182.1@76.5,98.75 76.6,98.65 pad.@77.6,98.65
  BOTTOM w0.6: pad.@77.6,98.65 PC7.5@78.9,98.65
PC_GD_U8: D57.K pad.@77.6,89.4 PC8.5 R183.1 | length 3.9
  TOP w0.6: D57.K@76.6,90.9 76.6,89.6 R183.1@76.5,89.5 76.6,89.4 pad.@77.6,89.4
  BOTTOM w0.6: pad.@77.6,89.4 PC8.5@78.9,89.4
PC_GD_V1: D58.K pad.@106.25,116.85 PC9.5 R168.1 | length 3.9
  TOP w0.6: D58.K@104.75,115.85 106.05,115.85 R168.1@106.15,115.75 106.25,115.85 pad.@106.25,116.85
  BOTTOM w0.6: pad.@106.25,116.85 PC9.5@106.25,118.15
PC_GD_V2: D59.K pad.@115.5,116.85 PC10.5 R169.1 | length 3.9
  TOP w0.6: D59.K@114,115.85 115.3,115.85 R169.1@115.4,115.75 115.5,115.85 pad.@115.5,116.85
  BOTTOM w0.6: pad.@115.5,116.85 PC10.5@115.5,118.15
PC_GD_V3: D60.K pad.@124.75,116.85 PC11.5 R170.1 | length 3.9
  TOP w0.6: D60.K@123.25,115.85 124.55,115.85 R170.1@124.65,115.75 124.75,115.85 pad.@124.75,116.85
  BOTTOM w0.6: pad.@124.75,116.85 PC11.5@124.75,118.15
PC_GD_V4: D62.K pad.@134,116.85 PC12.5 R171.1 | length 3.9
  TOP w0.6: D62.K@132.5,115.85 133.8,115.85 R171.1@133.9,115.75 134,115.85 pad.@134,116.85
  BOTTOM w0.6: pad.@134,116.85 PC12.5@134,118.15
PC_GD_V5: D61.K pad.@146.85,116.85 PC13.5 R172.1 | length 3.9
  TOP w0.6: D61.K@145.35,115.85 146.65,115.85 R172.1@146.75,115.75 146.85,115.85 pad.@146.85,116.85
  BOTTOM w0.6: pad.@146.85,116.85 PC13.5@146.85,118.15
